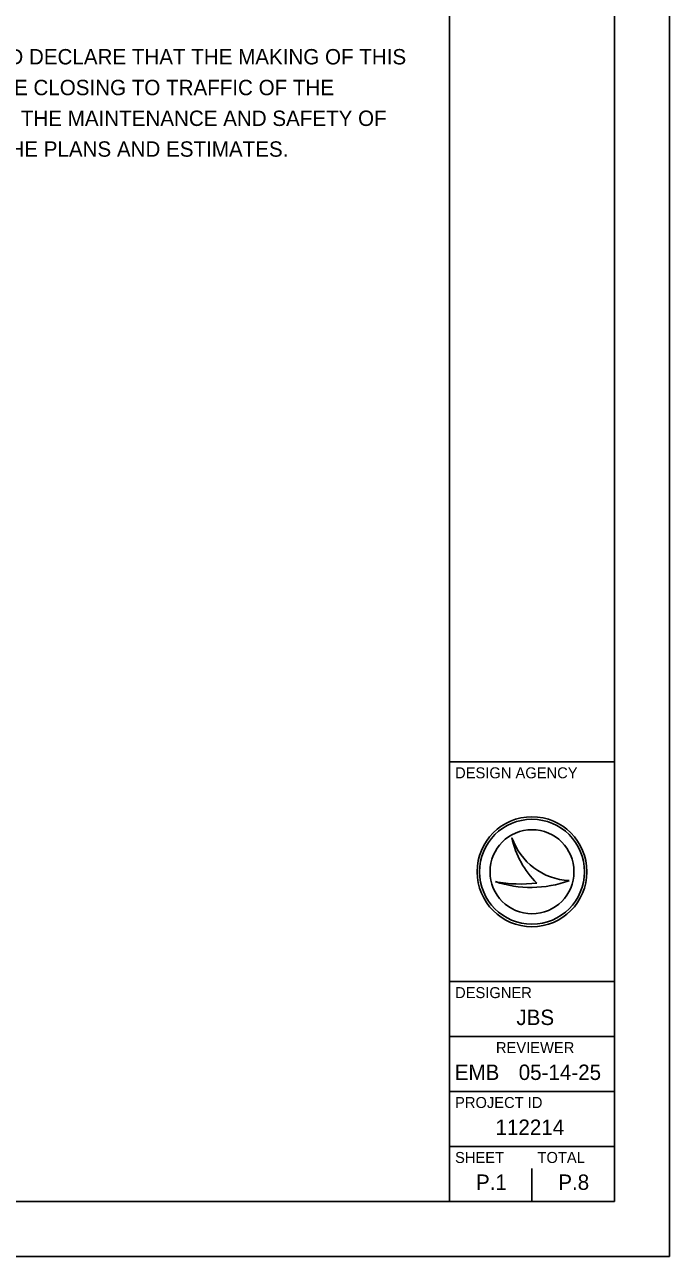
# Model space of a CAD drawing. Extents: x 0 to 34, y 0 to 22.
# Drawn here: x 28.13 to 34, y 0 to 11.21 of the extents above; entities that cross this region are included whole.
import ezdxf

# ---------------------------------------------------------------- set-up
doc = ezdxf.new("R2010")
doc.units = 0
for name, color, linetype in [('Default', 7, 'Continuous'), ('SH_Border', 7, 'Continuous'), ('SH_Cut_Line', 7, 'Continuous'), ('SH_Data', 7, 'Continuous')]:
    doc.layers.add(name, color=color, linetype=linetype)

msp = doc.modelspace()

# ---------------------------------------------------------------- linework, layer by layer
at = {"layer": 'SH_Border'}
for p, q in [((32, 0.5), (32, 21.5)), ((32, 4.5), (33.5, 4.5)), ((32, 2.5), (33.5, 2.5)), ((32, 2), (33.5, 2)), ((32, 1.5), (33.5, 1.5)), ((32, 1), (33.5, 1))]:
    msp.add_line(p, q, dxfattribs=at)
msp.add_lwpolyline([(1.5, 21.5), (33.5, 21.5), (33.5, 0.5), (1.5, 0.5)], close=True, dxfattribs=at)
at = {"layer": 'SH_Cut_Line'}
msp.add_lwpolyline([(0, 0), (34, 0), (34, 22), (0, 22)], close=True, dxfattribs=at)
at = {"layer": 'SH_Data'}
for p, q in [((32.567, 3.81), (32.567, 3.81)), ((32.75, 3.5), (32.75, 3.5)), ((32.417, 3.41), (32.417, 3.41)), ((33.087, 3.419), (33.087, 3.419)), ((32.75, 0.5), (32.75, 0.8)), ((32.375, 0.675), (32.375, 0.675))]:
    msp.add_line(p, q, dxfattribs=at)
for radius in [0.5, 0.477, 0.477, 0.382]:
    msp.add_circle((32.75, 3.5), radius, dxfattribs=at)
for centre, radius, start, end in [((33.116, 3.998), 0.58, 198.9257, 198.9319), ((33.347, 3.97), 0.796, 191.6379, 191.6421), ((33.116, 3.998), 0.58, 198.9319, 267.1657), ((33.347, 3.97), 0.796, 191.6421, 226.0947), ((32.739, 4.37), 1.013, 251.4576, 290.0832), ((32.648, 4.654), 1.266, 259.4964, 259.4995), ((32.739, 4.37), 1.013, 251.4527, 251.4576), ((32.648, 4.654), 1.266, 259.4995, 276.6672)]:
    msp.add_arc(centre, radius, start, end, dxfattribs=at)

# ---------------------------------------------------------------- texts
at = {"layer": 'Default'}
for s, p in [('I HEREBY APPROVE THESE PLANS AND DECLARE THAT THE MAKING OF THIS', (24.5, 10.846)), ('IMPROVEMENT WILL NOT REQUIRE THE CLOSING TO TRAFFIC OF THE', (24.5, 10.566)), ('HIGHWAY AND THAT PROVISIONS FOR THE MAINTENANCE AND SAFETY OF', (24.5, 10.286)), ('TRAFFIC WILL BE AS SET FORTH ON THE PLANS AND ESTIMATES.', (24.5, 10.006))]:
    msp.add_text(s, height=0.14, dxfattribs=at).set_placement(p)
at = {"layer": 'SH_Data'}
for s, height, p in [('DESIGN AGENCY', 0.1, (32.05, 4.35)), ('DESIGNER', 0.1, (32.05, 2.35)), ('JBS', 0.14, (32.608, 2.105)), ('REVIEWER', 0.1, (32.422, 1.85)), ('EMB', 0.14, (32.047, 1.605)), ('05-14-25', 0.14, (32.629, 1.605)), ('PROJECT ID', 0.1, (32.05, 1.35)), ('112214', 0.14, (32.418, 1.105)), ('SHEET', 0.1, (32.05, 0.85)), ('TOTAL', 0.1, (32.8, 0.85)), ('P.1', 0.14, (32.24, 0.605)), ('P.8', 0.14, (32.989, 0.605))]:
    msp.add_text(s, height=height, dxfattribs=at).set_placement(p)

doc.saveas('drawing.dxf')
